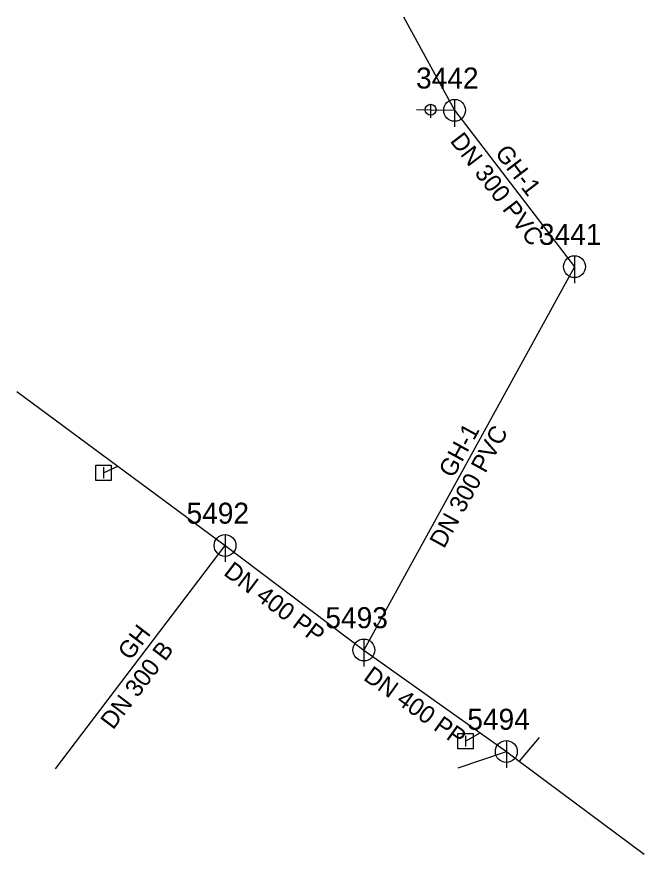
# Model space of a CAD drawing. Extents: x -466022.7 to -465965.2, y -1118441.8 to -1118365.
import ezdxf

# ---------------------------------------------------------------- set-up
doc = ezdxf.new("R2010")
doc.units = 0
for name, color, linetype in [('_pripojka_kanal_destova_prevzato_z_dokumentace_', 7, 'Continuous'), ('_pripojka_kanal_jednotna_priblizne_', 7, 'Continuous'), ('_stoka_jednotna_smvak_prevzato_z_dokumentace_', 7, 'Continuous'), ('Default', 7, 'Continuous'), ('MoLevel 119', 7, 'Continuous'), ('MoLevel 120', 7, 'Continuous'), ('MoLevel 57', 7, 'Continuous'), ('MoLevel 63', 7, 'Continuous'), ('MoLevel 68', 7, 'Continuous'), ('MoLevel 69', 7, 'Continuous')]:
    doc.layers.add(name, color=color, linetype=linetype)

# ---------------------------------------------------------------- blocks, each defined once
blk = doc.blocks.new('_vpust_')
at = {"layer": 'Default'}
blk.add_line((0, 0.000025), (0, -0.000025), dxfattribs=at)
blk.add_lwpolyline([(-0.000035, 0.000035), (0.000035, 0.000035), (0.000035, -0.000035), (-0.000035, -0.000035), (-0.000035, 0.000035)], dxfattribs=at)
blk = doc.blocks.new('_sachta_kanal_prip_')
at = {"layer": 'Default'}
blk.add_line((0, 0.00005), (0, -0.000075), dxfattribs=at)
blk.add_circle((0, 0), 0.00005, dxfattribs=at)
blk = doc.blocks.new('_sachta_kanal_prevzato_z_dokumentace_')
at = {"layer": 'Default'}
blk.add_line((0, 0.00005), (0, -0.000075), dxfattribs=at)
blk.add_circle((0, 0), 0.00005, dxfattribs=at)

msp = doc.modelspace()

# ---------------------------------------------------------------- linework, layer by layer
at = {"layer": '_pripojka_kanal_destova_prevzato_z_dokumentace_'}
for p, q in [((-466014.73, -1118406.79), (-466013.416, -1118406.196)), ((-465981.55, -1118431.4), (-465980.229, -1118430.631))]:
    msp.add_line(p, q, dxfattribs=at)
at = {"layer": '_pripojka_kanal_jednotna_priblizne_'}
for p, q in [((-465986.063, -1118373.495), (-465984.76, -1118373.518)), ((-465984.76, -1118373.518), (-465982.561, -1118373.568)), ((-465974.809, -1118431.048), (-465976.633, -1118433.235)), ((-465982.233, -1118433.852), (-465977.82, -1118432.35))]:
    msp.add_line(p, q, dxfattribs=at)
at = {"layer": '_stoka_jednotna_smvak_prevzato_z_dokumentace_'}
for p, q in [((-465987.235, -1118364.99), (-465982.561, -1118373.568)), ((-465982.561, -1118373.568), (-465971.58, -1118387.9)), ((-465971.58, -1118387.9), (-465990.87, -1118423.04)), ((-466019.129, -1118433.919), (-466003.59, -1118413.46)), ((-466003.59, -1118413.46), (-465990.87, -1118423.04))]:
    msp.add_line(p, q, dxfattribs=at)
for points in [[(-466022.672, -1118399.352), (-466013.416, -1118406.196), (-466003.59, -1118413.46)], [(-465990.87, -1118423.04), (-465980.229, -1118430.631), (-465977.82, -1118432.35)], [(-465977.82, -1118432.35), (-465976.633, -1118433.235), (-465965.188, -1118441.762)]]:
    msp.add_lwpolyline(points, dxfattribs=at)

# ---------------------------------------------------------------- block references
at = {"layer": 'MoLevel 119', "xscale": 20000, "yscale": 20000}
for p in [(-465982.561, -1118373.568), (-465971.58, -1118387.9), (-466003.59, -1118413.46), (-465990.87, -1118423.04), (-465977.82, -1118432.35)]:
    msp.add_blockref('_sachta_kanal_prevzato_z_dokumentace_', p, dxfattribs=at)
at = {"layer": 'MoLevel 57', "xscale": 10000, "yscale": 10000}
msp.add_blockref('_sachta_kanal_prip_', (-465984.76, -1118373.518), dxfattribs=at)
at = {"layer": 'MoLevel 63', "xscale": 20000, "yscale": 20000}
for p in [(-466014.73, -1118406.79), (-465981.55, -1118431.4)]:
    msp.add_blockref('_vpust_', p, dxfattribs=at)

# ---------------------------------------------------------------- texts
at = {"layer": 'MoLevel 120'}
for s, p in [('3442', (-465986.092, -1118371.568)), ('3441', (-465974.836, -1118385.9)), ('5492', (-466007.121, -1118411.46)), ('5493', (-465994.401, -1118421.04)), ('5494', (-465981.397, -1118430.35))]:
    msp.add_text(s, height=1.9259, dxfattribs=at).set_placement(p)
at = {"layer": 'MoLevel 68'}
for s, rotation, p in [('DN 300 PVC', 307.45889, (-465983.039, -1118376.383)), ('DN 300 PVC', 61.23555, (-465983.533, -1118413.809)), ('DN 400 PP', 323.01497, (-466003.812, -1118416.102)), ('DN 300 B', 52.78264, (-466013.849, -1118430.42)), ('DN 400 PP', 324.49698, (-465991.001, -1118425.718))]:
    msp.add_text(s, height=1.6049, rotation=rotation, dxfattribs=at).set_placement(p)
at = {"layer": 'MoLevel 69'}
for s, rotation, p in [('GH-1', 307.45889, (-465978.93, -1118377.507)), ('GH-1', 61.23555, (-465982.696, -1118407.35)), ('GH', 52.78264, (-466012.261, -1118424.076))]:
    msp.add_text(s, height=1.6049, rotation=rotation, dxfattribs=at).set_placement(p)

doc.saveas('drawing.dxf')
